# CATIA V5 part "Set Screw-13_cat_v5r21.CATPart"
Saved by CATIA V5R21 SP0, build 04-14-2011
Part number: Set Screw-13
Bounding box of the stored display mesh (mm): x -5.916 to 5.916, y -5.998 to 5.998, z -1.5 to 16
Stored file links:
  D:\CATIA V5R21 E-RESOURCES\CATIA-V5R21\catia-v5r21-Tut\c13-catia-v5r21-tut\c13-catia-v5r21-tut02\Bench Vice\Set Screw-13_cat_v5r21.CATPart
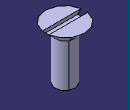
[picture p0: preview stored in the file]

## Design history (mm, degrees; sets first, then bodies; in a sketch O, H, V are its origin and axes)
Body1 (main body)
  Sketch1 on yz-plane, origin (0, 0, 0), H (0, 1, 0), V (0, 0, 1)
    point P1 (0, -1.5)
    line L1 (0, -1.5) -> (3, 0)
    point P2 (3, 0)
    line L2 (3, 0) -> (3, 13)
    line L3 (3, 13) -> (6, 16)
    point P4 (6, 16)
    line L4 (6, 16) -> (0, 16)
    point P5 (0, 16)
    line L5 (0, 16) -> (0, -1.5)
    length L2 = 13
    distance L2 L5 = 3
    distance H P1 = 1.5
    distance P4 L5 = 6
    angle L3 L5 = 45
    coincidence: P1 V, P2 H, P5 V
    vertical: L2 V, L5 V
    horizontal: L4 H
  Shaft1: profile Sketch1, axis edge of Sketch1, angle 360
  Sketch2 on yz-plane, origin (0, 0, 0), H (0, 1, 0), V (0, 0, 1)
    line L1 (-1, 16) -> (1, 16)
    line L2 (1, 16) -> (1, 15)
    line L3 (1, 15) -> (-1, 15)
    line L4 (-1, 15) -> (-1, 16)
    reference projected line E1 (-6, 16) -> (6, 16) from edge of Shaft1
    distance V L2 = 1
    length L1 = 2
    length L2 = 1
    horizontal: L1 H, L3 H
    vertical: L2 V, L4 V
    coincidence: L1 E1
  Pocket1: profile Sketch2, direction (-1, 0, 0), length 16, mirrored extent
